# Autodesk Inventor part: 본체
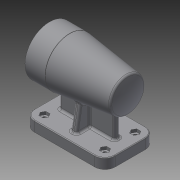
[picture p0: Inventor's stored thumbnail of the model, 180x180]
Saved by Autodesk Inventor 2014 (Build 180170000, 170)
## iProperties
Created: 2017-01
Part Number: 본체
Material: 일반
Document SubType Name: Modeling
Designer: user
Density: 1 g/cm^3
Appearance: 기본값
Mass: 295.591 g
Surface Area: 666.986 cm^2
Volume: 295.591 cm^3
Author: user
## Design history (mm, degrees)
sketch "스케치2"
  geometry: L1 (-56, 35)-(56, 35); L2 (56, 35)-(56, -35); L3 (56, -35)-(-56, -35); L4 (-56, -35)-(-56, 35); L5 (-56, 35)-(56, -35); L6 (56, 35)-(-56, -35); 1 further point
  constraints: 12 end point, 2 midpoint, 2 parallel, 1 horizontal, 1 perpendicular
  dimensions: "d6" = 112 distance of L2.end L3.end; "d7" = 70 distance of L1.end L2.end
extrude "돌출1" new body sketch "스케치2" distance "d8" = 14; taper "d9" = 0 deg
fillet "모깎기2" dims "d10" = 14
fillet "모깎기3" dims "d11" = 14
sketch "스케치3"
  geometry: L1 (0, 0)-(0, 74); L2 (-56, 74)-(56, 74); L3 (56, 74)-(56, 108); L4 (56, 108)-(28, 108); L5 (28, 108)-(-52.27, 98.144); A1 r 80 centre (24, 74) between (-52.27, 98.144) and (-56, 74)
  constraints: 10 end point, 3 perpendicular, 2 point on circle, 1 centre point, 1 midpoint, 1 point on line, 1 vertical
  dimensions: "d12" = 74 distance of L1.end L1.start; "d13" = 68 diameter of L4 L2; "d14" = 28 distance from line of L4.end L3; "d15" = 7 deg angle of L5 L4; "d16" = 80 radius of A1; "d17" = 112 distance from line of L3 L2.start
revolve "회전2" sketch "스케치3" stored, may be unused: angle "d18" = 90 deg
sketch "스케치4"
  geometry: L1 (28, 40)-(28, 108) reference; L2 (56, 40)-(56, 108) reference; L3 (56, 74)-(-103.727, 74); L4 (56, 95)-(41, 95); L5 (41, 95)-(41, 95); L6 (38, 98)-(-10, 98); L7 (-13, 95)-(-13, 95); L8 (-13, 95)-(-24.7, 95); L9 (-25, 94.7)-(-25, 91.5); L10 (-25, 91.5)-(-42.7, 91.5); L11 (-43, 91.2)-(-43, 90); L12 (-43, 90)-(-46.7, 90); L13 (-47, 89.7)-(-47, 84.5); L14 (-47, 84.5)-(-47, 84.5); L15 (-50, 81.5)-(-50, 74); A1 r 0.3 centre (-46.7, 89.7) between (-46.7, 90) and (-47, 89.7); A2 r 0.3 centre (-42.7, 91.2) between (-42.7, 91.5) and (-43, 91.2); A3 r 0.3 centre (-24.7, 94.7) between (-24.7, 95) and (-25, 94.7); A4 r 3 centre (-47, 81.5) between (-47, 84.5) and (-50, 81.5); A5 r 3 centre (-10, 95) between (-10, 98) and (-13, 95); A6 r 3 centre (38, 95) between (41, 95) and (38, 98); 7 further points
  constraints: 26 end point, 14 point on line, 12 point on circle, 12 tangent, 10 perpendicular, 6 centre point, 4 equal radius, 3 parallel, 1 midpoint
  dimensions: "d20" = 42 diameter of L4 L3; "d21" = 48 diameter of L6 L3; "d22" = 42 diameter of L8 L3; "d23" = 35 diameter of L10 L3; "d24" = 32 diameter of L12 L3; "d25" = 15 distance of L4.start L4.end; "d26" = 54 distance of point (41, 98) point (-13, 98); "d27" = 12 distance of L7.end point (-25, 95); "d28" = 18 distance of L9.end point (-43, 91.5); "d29" = 4 distance of L11.end point (-47, 90); "d30" = 3 distance of L13.end point (-50, 84.5); "d31" = 21 diameter of L14 L3; "d32" = 0.3 radius of A1; "d33" = 3 radius of A4
revolve "회전3" sketch "스케치4" stored, may be unused: angle "d34" = 90 deg
sketch "스케치5"
  geometry: C1 r 34 at (0, 0) reference; A1 r 26 centre (0, 0) between (0, 26) and (26, 0); 3 further points
  constraints: 4 point on circle, 1 centre point, 1 coincident
  dimensions: "d35" = 52 diameter of A1
hole "구멍1" sketch "스케치5" at (0, 26), (26, 0), (0, -26), (-26, 0) diameter "d36" = 3.242; stored, may be unused: countersink angle "d40" = 90 deg, drill point angle "d42" = 118 deg; dims "d37" = 8, "d38" = 4, "d39" = 2, "d41" = 11
chamfer "모따기1" distance "d43" = 1; stored, may be unused: second distance "d44" = 2, angle "d45" = 45 deg
fillet "모깎기4" dims "d46" = 3
sketch "스케치6"
  geometry: L1 (56, -21)-(56, 21) reference; L2 (42, 35)-(-42, 35) reference; L3 (-56, 21)-(-56, -21) reference; L4 (-38, 4)-(38, 4); L5 (38, 4)-(38, -4); L6 (38, -4)-(-38, -4); L7 (-38, -4)-(-38, 4); L8 (-38, 4)-(38, -4); L9 (38, 4)-(-38, -4); 2 further points
  constraints: 12 end point, 3 midpoint, 2 parallel, 1 horizontal, 1 perpendicular
  dimensions: "d47" = 35 distance from line of point (0, 0) L2 (derived); "d48" = 8 distance between parallel lines of L6 L4; "d49" = 56 distance from line of point (0, 4) L1 (derived); "d50" = 18 distance between parallel lines of L5 L1; "d51" = 18 distance between parallel lines of L3 L7 (derived)
extrude "돌출2" join sketch "스케치6" stored distance "d52" = 14; taper "d53" = 0 deg
sketch "스케치7"
  geometry: L1 (21, 14)-(-21, 14) reference; L2 (-35, 0)-(-35, 14) reference; L3 (-35, 14)-(-21, 14) reference; L4 (35, 14)-(35, 0) reference; L5 (21, 14)-(35, 14) reference; L6 (35, 14)-(35, 0) reference; L7 (35, 0)-(21, 0) reference; L8 (21, 0)-(21, 14) reference; L9 (-15.923, 54.137)-(-23, 14); L10 (15.923, 54.137)-(23, 14); 1 further point
  constraints: 4 end point, 2 point on line
  dimensions: "d54" = 12 distance from line of L9.end L2; "d55" = 12 distance from line of L10.end L4; "d56" = 100 deg angle of L9 L3; "d57" = 100 deg angle of L10 L5; "d58" = 40.75605 distance of L9.start L9.end; "d59" = 40.756 distance of L10.start L10.end
  node "투영된 루프2"
feature "리브1" dims "d60" = 1, "d61" = 8, "d62" = 0, "d63" = 0, "d64" = 1, "d65" = 1
feature "리브2" dims "d66" = 1, "d67" = 8, "d68" = 0, "d69" = 0, "d70" = 1, "d71" = 1
fillet "모깎기5" dims "d72" = 3
fillet "모깎기6" dims "d73" = 3
fillet "모깎기7" dims "d74" = 3
sketch "스케치8"
  geometry: L1 (0, 0)-(84, 0) reference; L2 (-14, 0)-(-14, -14) reference; 2 further points
  constraints: 1 other
  dimensions: "d75" = 56 distance from line of point (42, -4) L2; "d76" = 4 distance from line of point (42, -4) L1
feature "엠보싱1" sketch "스케치8" dims "d6" = 112, "d7" = 70, "d12" = 74, "d13" = 68, "d14" = 28, "d15" = 7 deg, "d16" = 80, "d17" = 112, "d77" = 0.5, "d78" = 0
node "작업 평면1"
fillet "모깎기9" dims "d83" = 1
sketch "스케치9"
  geometry: L1 (-39.113, 26)-(-36.226, 21); L2 (-36.226, 21)-(-39.113, 16); L3 (-39.113, 16)-(-44.887, 16); L4 (-44.887, 16)-(-47.774, 21); L5 (-47.774, 21)-(-44.887, 26); L6 (-44.887, 26)-(-39.113, 26); L7 (36.226, 21)-(39.113, 26); L8 (44.887, 26)-(47.774, 21); L9 (47.774, 21)-(44.887, 16); L10 (44.887, 16)-(39.113, 16); L11 (39.113, 16)-(36.226, 21); L12 (39.113, -16)-(44.887, -16); L13 (36.226, -21)-(39.113, -16); L14 (44.887, -16)-(47.774, -21); L15 (47.774, -21)-(44.887, -26); L16 (44.887, -26)-(39.113, -26); L17 (39.113, -26)-(36.226, -21); L18 (-44.887, -16)-(-39.113, -16); L19 (-47.774, -21)-(-44.887, -16); L20 (-39.113, -16)-(-36.226, -21); L21 (-36.226, -21)-(-39.113, -26); L22 (-39.113, -26)-(-44.887, -26); L23 (-44.887, -26)-(-47.774, -21); L24 (39.113, 26)-(44.887, 26); A1 r 13 centre (-42, 21) between (-42, 34) and (-55, 21) reference; 5 further points
  constraints: 48 end point, 1 coincident, 1 parallel, 40 other
extrude "돌출3" cut sketch "스케치9" distance "d88" = 4; taper "d89" = 0 deg
sketch "스케치10"
  geometry: C1 r 2.5 at (-42, 21); C2 r 2.5 at (42, 21); C3 r 2.5 at (42, -21); C4 r 2.5 at (-42, -21); A1 r 14 centre (42, -21) between (42, -35) and (56, -21) reference; A2 r 14 centre (42, 21) between (56, 21) and (42, 35) reference; A3 r 14 centre (-42, 21) between (-42, 35) and (-56, 21) reference; A4 r 14 centre (-42, -21) between (-56, -21) and (-42, -35) reference; 1 further point
  constraints: 4 centre point, 4 coincident
  dimensions: "d90" = 5 diameter of C1; "d91" = 5 diameter of C2; "d92" = 5 diameter of C3; "d93" = 5 diameter of C4
extrude "돌출4" cut sketch "스케치10" stored distance "d94" = 4; taper "d95" = 0 deg
node "솔리드2"
node "투영된 루프1"
other parameters: "d81" = -7
